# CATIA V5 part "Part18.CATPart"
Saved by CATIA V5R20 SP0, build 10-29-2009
Part number: 9SA160016-C_acabado
Revision: ANY
Definition: UNKNOWN
Nomenclature: 9SA160016-C_acabado
Source: Unknown
Bounding box of the stored display mesh (mm): x -8 to 8, y 0 to 16, z -8 to 8
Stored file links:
  C:\Users\Utente\Desktop\IO LAVORO\3D X SITO CF\CUMSA\3D files SA\SA 160416\Part18.CATPart
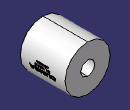
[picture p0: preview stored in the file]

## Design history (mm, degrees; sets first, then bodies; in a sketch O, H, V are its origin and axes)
Body1 "Envolver1" (main body)
  Solid1: solid without history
